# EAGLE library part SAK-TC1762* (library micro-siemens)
Infineon TriCore NG (Next Generation) 32bit Microcontroller/DSP
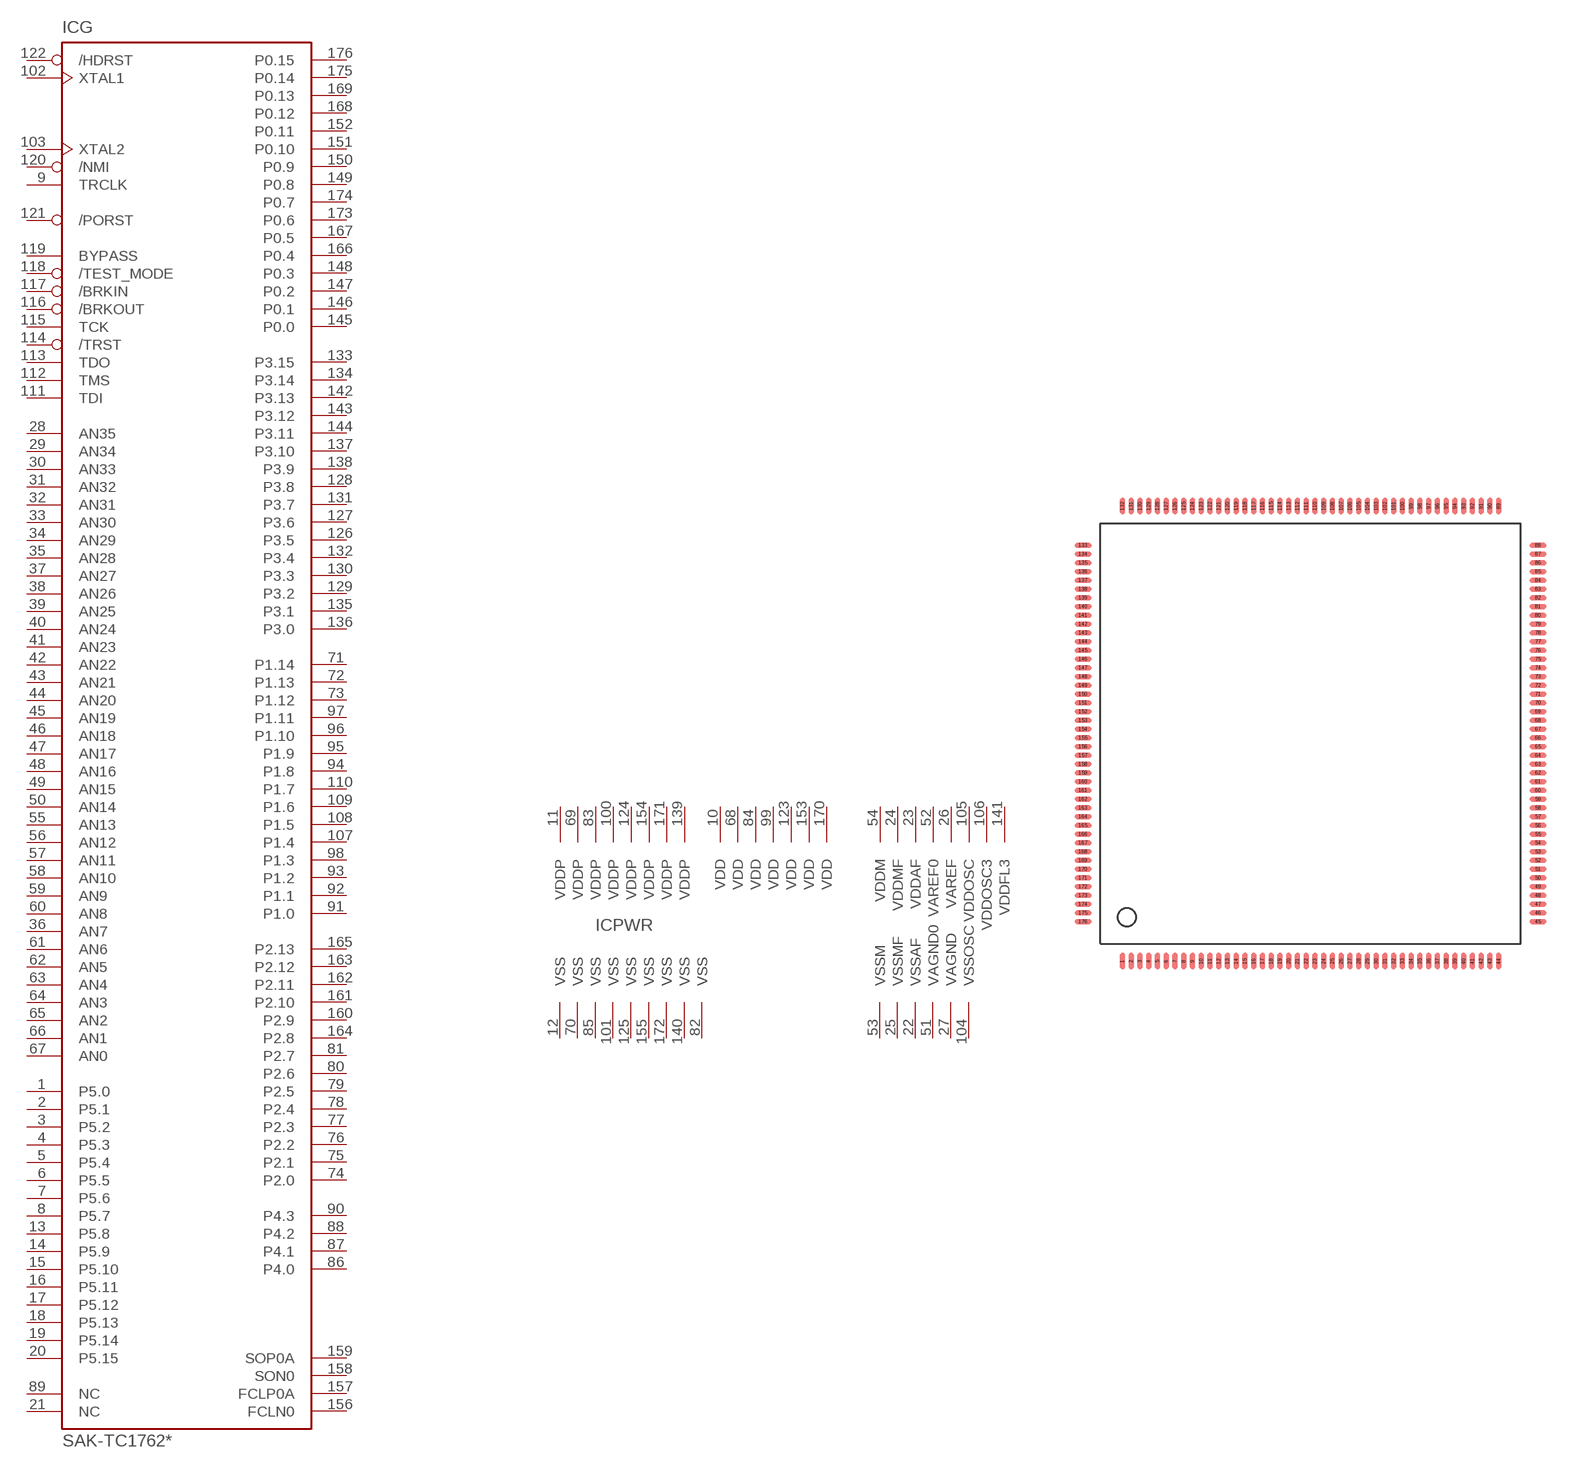
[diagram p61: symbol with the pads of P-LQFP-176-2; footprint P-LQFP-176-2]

Designator prefix IC; gates G=TC1762 PWR=PWR_TC1762

## SAK-TC1762 (OC_FARNELL: unknown; OC_NEWARK: unknown)  [P-LQFP-176-2]
1  G:P5.0  pas
2  G:P5.1  pas
3  G:P5.2  pas
4  G:P5.3  pas
5  G:P5.4  pas
6  G:P5.5  pas
7  G:P5.6  pas
8  G:P5.7  pas
9  G:TRCLK  pas
10  PWR:VDD  pwr
11  PWR:VDDP  pwr
12  PWR:VSS  pwr
13  G:P5.8  pas
14  G:P5.9  pas
15  G:P5.10  pas
16  G:P5.11  pas
17  G:P5.12  pas
18  G:P5.13  pas
19  G:P5.14  pas
20  G:P5.15  pas
21  G:NC  pas
22  PWR:VSSAF  pwr
23  PWR:VDDAF  pwr
24  PWR:VDDMF  pwr
25  PWR:VSSMF  pwr
26  PWR:VAREF  pwr
27  PWR:VAGND  pwr
28  G:AN35  pas
29  G:AN34  pas
30  G:AN33  pas
31  G:AN32  pas
32  G:AN31  pas
33  G:AN30  pas
34  G:AN29  pas
35  G:AN28  pas
36  G:AN7  pas
37  G:AN27  pas
38  G:AN26  pas
39  G:AN25  pas
40  G:AN24  pas
41  G:AN23  pas
42  G:AN22  pas
43  G:AN21  pas
44  G:AN20  pas
45  G:AN19  pas
46  G:AN18  pas
47  G:AN17  pas
48  G:AN16  pas
49  G:AN15  pas
50  G:AN14  pas
51  PWR:VAGND0  pwr
52  PWR:VAREF0  pwr
53  PWR:VSSM  pwr
54  PWR:VDDM  pwr
55  G:AN13  pas
56  G:AN12  pas
57  G:AN11  pas
58  G:AN10  pas
59  G:AN9  pas
60  G:AN8  pas
61  G:AN6  pas
62  G:AN5  pas
63  G:AN4  pas
64  G:AN3  pas
65  G:AN2  pas
66  G:AN1  pas
67  G:AN0  pas
68  PWR:VDD  pwr
69  PWR:VDDP  pwr
70  PWR:VSS  pwr
71  G:P1.14  pas
72  G:P1.13  pas
73  G:P1.12  pas
74  G:P2.0  pas
75  G:P2.1  pas
76  G:P2.2  pas
77  G:P2.3  pas
78  G:P2.4  pas
79  G:P2.5  pas
80  G:P2.6  pas
81  G:P2.7  pas
82  PWR:VSS  pwr
83  PWR:VDDP  pwr
84  PWR:VDD  pwr
85  PWR:VSS  pwr
86  G:P4.0  pas
87  G:P4.1  pas
88  G:P4.2  pas
89  G:NC  pas
90  G:P4.3  pas
91  G:P1.0  pas
92  G:P1.1  pas
93  G:P1.2  pas
94  G:P1.8  pas
95  G:P1.9  pas
96  G:P1.10  pas
97  G:P1.11  pas
98  G:P1.3  pas
99  PWR:VDD  pwr
100  PWR:VDDP  pwr
101  PWR:VSS  pwr
102  G:XTAL1  pas
103  G:XTAL2  pas
104  PWR:VSSOSC  pwr
105  PWR:VDDOSC  pwr
106  PWR:VDDOSC3  pwr
107  G:P1.4  pas
108  G:P1.5  pas
109  G:P1.6  pas
110  G:P1.7  pas
111  G:TDI  pas
112  G:TMS  pas
113  G:TDO  pas
114  G:/TRST  pas
115  G:TCK  pas
116  G:/BRKOUT  pas
117  G:/BRKIN  pas
118  G:/TEST_MODE  pas
119  G:BYPASS  pas
120  G:/NMI  pas
121  G:/PORST  pas
122  G:/HDRST  pas
123  PWR:VDD  pwr
124  PWR:VDDP  pwr
125  PWR:VSS  pwr
126  G:P3.5  pas
127  G:P3.6  pas
128  G:P3.8  pas
129  G:P3.2  pas
130  G:P3.3  pas
131  G:P3.7  pas
132  G:P3.4  pas
133  G:P3.15  pas
134  G:P3.14  pas
135  G:P3.1  pas
136  G:P3.0  pas
137  G:P3.10  pas
138  G:P3.9  pas
139  PWR:VDDP  pwr
140  PWR:VSS  pwr
141  PWR:VDDFL3  pwr
142  G:P3.13  pas
143  G:P3.12  pas
144  G:P3.11  pas
145  G:P0.0  pas
146  G:P0.1  pas
147  G:P0.2  pas
148  G:P0.3  pas
149  G:P0.8  pas
150  G:P0.9  pas
151  G:P0.10  pas
152  G:P0.11  pas
153  PWR:VDD  pwr
154  PWR:VDDP  pwr
155  PWR:VSS  pwr
156  G:FCLN0  pas
157  G:FCLP0A  pas
158  G:SON0  pas
159  G:SOP0A  pas
160  G:P2.9  pas
161  G:P2.10  pas
162  G:P2.11  pas
163  G:P2.12  pas
164  G:P2.8  pas
165  G:P2.13  pas
166  G:P0.4  pas
167  G:P0.5  pas
168  G:P0.12  pas
169  G:P0.13  pas
170  PWR:VDD  pwr
171  PWR:VDDP  pwr
172  PWR:VSS  pwr
173  G:P0.6  pas
174  G:P0.7  pas
175  G:P0.14  pas
176  G:P0.15  pas

## Footprint P-LQFP-176-2 (pad centres in mm)
P-LQFP-176-2 with rounded pads
smd 0.3 x 1: 1 -10.75,-13; 2 -10.25,-13; 3 -9.75,-13; 4 -9.25,-13; 5 -8.75,-13; 6 -8.25,-13; 7 -7.75,-13; 8 -7.25,-13; 9 -6.75,-13; 10 -6.25,-13; 11 -5.75,-13; 12 -5.25,-13; 13 -4.75,-13; 14 -4.25,-13; 15 -3.75,-13; 16 -3.25,-13; 17 -2.75,-13; 18 -2.25,-13; 19 -1.75,-13; 20 -1.25,-13; 21 -0.75,-13; 22 -0.25,-13; 23 0.25,-13; 24 0.75,-13; 25 1.25,-13; 26 1.75,-13; 27 2.25,-13; 28 2.75,-13; 29 3.25,-13; 30 3.75,-13; 31 4.25,-13; 32 4.75,-13; 33 5.25,-13; 34 5.75,-13; 35 6.25,-13; 36 6.75,-13; 37 7.25,-13; 38 7.75,-13; 39 8.25,-13; 40 8.75,-13; 41 9.25,-13; 42 9.75,-13; 43 10.25,-13; 44 10.75,-13; 89 10.75,13; 90 10.25,13; 91 9.75,13; 92 9.25,13; 93 8.75,13; 94 8.25,13; 95 7.75,13; 96 7.25,13; 97 6.75,13; 98 6.25,13; 99 5.75,13; 100 5.25,13; 101 4.75,13; 102 4.25,13; 103 3.75,13; 104 3.25,13; 105 2.75,13; 106 2.25,13; 107 1.75,13; 108 1.25,13; 109 0.75,13; 110 0.25,13; 111 -0.25,13; 112 -0.75,13; 113 -1.25,13; 114 -1.75,13; 115 -2.25,13; 116 -2.75,13; 117 -3.25,13; 118 -3.75,13; 119 -4.25,13; 120 -4.75,13; 121 -5.25,13; 122 -5.75,13; 123 -6.25,13; 124 -6.75,13; 125 -7.25,13; 126 -7.75,13; 127 -8.25,13; 128 -8.75,13; 129 -9.25,13; 130 -9.75,13; 131 -10.25,13; 132 -10.75,13
smd 1 x 0.3: 45 13,-10.75; 46 13,-10.25; 47 13,-9.75; 48 13,-9.25; 49 13,-8.75; 50 13,-8.25; 51 13,-7.75; 52 13,-7.25; 53 13,-6.75; 54 13,-6.25; 55 13,-5.75; 56 13,-5.25; 57 13,-4.75; 58 13,-4.25; 59 13,-3.75; 60 13,-3.25; 61 13,-2.75; 62 13,-2.25; 63 13,-1.75; 64 13,-1.25; 65 13,-0.75; 66 13,-0.25; 67 13,0.25; 68 13,0.75; 69 13,1.25; 70 13,1.75; 71 13,2.25; 72 13,2.75; 73 13,3.25; 74 13,3.75; 75 13,4.25; 76 13,4.75; 77 13,5.25; 78 13,5.75; 79 13,6.25; 80 13,6.75; 81 13,7.25; 82 13,7.75; 83 13,8.25; 84 13,8.75; 85 13,9.25; 86 13,9.75; 87 13,10.25; 88 13,10.75; 133 -13,10.75; 134 -13,10.25; 135 -13,9.75; 136 -13,9.25; 137 -13,8.75; 138 -13,8.25; 139 -13,7.75; 140 -13,7.25; 141 -13,6.75; 142 -13,6.25; 143 -13,5.75; 144 -13,5.25; 145 -13,4.75; 146 -13,4.25; 147 -13,3.75; 148 -13,3.25; 149 -13,2.75; 150 -13,2.25; 151 -13,1.75; 152 -13,1.25; 153 -13,0.75; 154 -13,0.25; 155 -13,-0.25; 156 -13,-0.75; 157 -13,-1.25; 158 -13,-1.75; 159 -13,-2.25; 160 -13,-2.75; 161 -13,-3.25; 162 -13,-3.75; 163 -13,-4.25; 164 -13,-4.75; 165 -13,-5.25; 166 -13,-5.75; 167 -13,-6.25; 168 -13,-6.75; 169 -13,-7.25; 170 -13,-7.75; 171 -13,-8.25; 172 -13,-8.75; 173 -13,-9.25; 174 -13,-9.75; 175 -13,-10.25; 176 -13,-10.75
